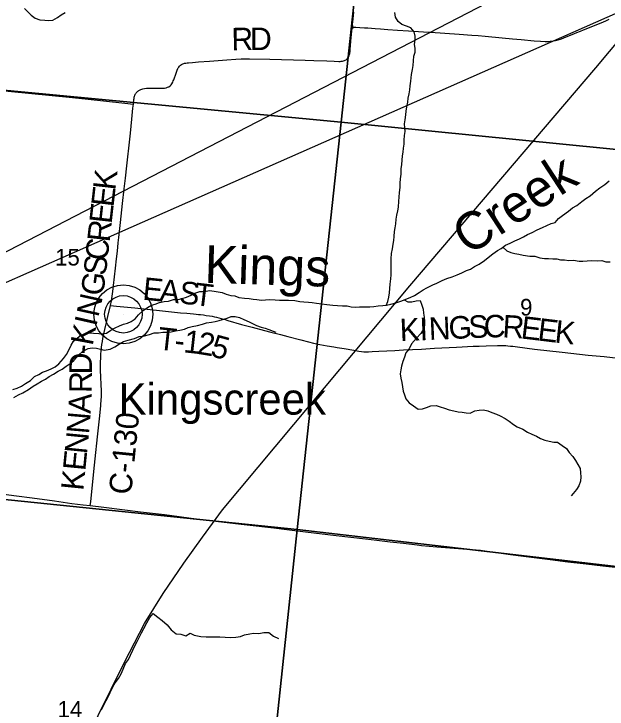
# Model space of a CAD drawing. Extents: x 831 to 1552, y 430 to 870.
# Drawn here: x 1016.19 to 1046.09, y 664.2 to 699.22 of the extents above; entities that cross this region are included whole.
import ezdxf

# ---------------------------------------------------------------- set-up
doc = ezdxf.new("R2010")
doc.units = 0
for name, color, linetype in [('GM_X_Corporation', 7, 'Continuous'), ('GM_X_County_Road', 7, 'Continuous'), ('GM_X_County_Road_Text', 7, 'Continuous'), ('GM_X_Minor_River', 7, 'Continuous'), ('GM_X_Minor_River_Text', 7, 'Continuous'), ('GM_X_Rail_Line', 7, 'Continuous'), ('GM_X_Section_Text', 7, 'Continuous'), ('GM_X_State_Route', 7, 'Continuous'), ('GM_X_Township_Road', 7, 'Continuous'), ('GM_X_Township_Road_Text', 7, 'Continuous'), ('GM_X_Unincorporated', 7, 'Continuous'), ('GM_X_Unincorporated_Location', 7, 'Continuous'), ('GM_X_Unincorporated_Text', 7, 'Continuous'), ('SH_Text', 7, 'Continuous')]:
    doc.layers.add(name, color=color, linetype=linetype)

msp = doc.modelspace()

# ---------------------------------------------------------------- linework, layer by layer
at = {"layer": 'GM_X_Corporation'}
for points in [[(1034.738, 712.834), (1032.694, 693.772), (1011.587, 695.769), (1013.944, 715)], [(1034.738, 712.834), (1054.834, 710.548), (1052.831, 691.774), (1032.694, 693.772)], [(1011.587, 695.769), (1032.694, 693.772), (1030.47, 673.244), (1009.676, 675.38)], [(1032.694, 693.772), (1052.831, 691.774), (1050.619, 670.912), (1030.47, 673.244)], [(1030.47, 673.244), (1028.346, 653.321), (1007.707, 655.818), (1009.676, 675.38)], [(1030.47, 673.244), (1050.619, 670.912), (1048.583, 651.419), (1028.346, 653.321)]]:
    msp.add_lwpolyline(points, close=True, dxfattribs=at)
at = {"layer": 'GM_X_County_Road'}
for points in [[(1033.297, 698.535), (1033.321, 698.543), (1033.344, 698.545), (1033.369, 698.547), (1033.392, 698.547), (1033.422, 698.546), (1033.632, 698.537), (1033.855, 698.527), (1034.028, 698.513), (1034.4, 698.484), (1034.673, 698.464), (1035.044, 698.439), (1035.527, 698.407), (1036.085, 698.37), (1036.841, 698.317), (1037.188, 698.293), (1038.639, 698.192), (1039.271, 698.148), (1039.593, 698.127), (1039.952, 698.099), (1040.794, 698.023), (1041.325, 697.971), (1041.759, 697.934), (1042.414, 697.872), (1042.737, 697.844), (1042.961, 697.833), (1043.136, 697.834), (1043.216, 697.84), (1043.311, 697.849), (1043.392, 697.863), (1043.484, 697.882), (1043.616, 697.918), (1043.783, 697.972), (1044.028, 698.064), (1044.41, 698.215), (1044.569, 698.282), (1044.754, 698.359), (1044.903, 698.42), (1045.791, 698.776), (1046.033, 698.877), (1046.19, 698.956)], [(1022.215, 694.682), (1022.223, 694.758), (1022.233, 694.837), (1022.243, 694.914), (1022.25, 694.966), (1022.26, 695.021), (1022.273, 695.071), (1022.286, 695.112), (1022.297, 695.14), (1022.311, 695.167), (1022.324, 695.191), (1022.34, 695.219), (1022.359, 695.244), (1022.377, 695.266), (1022.402, 695.291), (1022.419, 695.307), (1022.445, 695.328), (1022.467, 695.344), (1022.498, 695.364), (1022.53, 695.38), (1022.561, 695.395), (1022.595, 695.41), (1022.648, 695.428), (1022.688, 695.441), (1022.771, 695.46), (1022.881, 695.475), (1022.991, 695.481), (1023.189, 695.483), (1023.526, 695.48), (1023.641, 695.479), (1023.717, 695.479), (1023.787, 695.486), (1023.872, 695.504), (1023.943, 695.527), (1024.006, 695.554), (1024.063, 695.594), (1024.113, 695.642), (1024.159, 695.705), (1024.206, 695.788), (1024.229, 695.841), (1024.254, 695.903), (1024.365, 696.235), (1024.418, 696.386), (1024.454, 696.463), (1024.475, 696.509), (1024.5, 696.546), (1024.54, 696.594), (1024.588, 696.637), (1024.643, 696.674), (1024.706, 696.704), (1024.756, 696.722), (1024.794, 696.734), (1024.857, 696.747), (1024.92, 696.755), (1024.99, 696.76), (1025.203, 696.778), (1025.5, 696.799), (1026.046, 696.838), (1026.926, 696.904), (1027.384, 696.936), (1027.644, 696.95), (1027.793, 696.953), (1028.066, 696.953), (1029.097, 696.933), (1030.873, 696.892), (1031.307, 696.876), (1031.966, 696.854), (1032.34, 696.838), (1032.569, 696.828), (1032.64, 696.831), (1032.694, 696.836), (1032.755, 696.845), (1032.803, 696.854), (1032.85, 696.867), (1032.889, 696.885), (1032.932, 696.915), (1032.966, 696.94), (1032.999, 696.974), (1033.036, 697.019), (1033.067, 697.07), (1033.085, 697.109), (1033.104, 697.168), (1033.12, 697.231), (1033.127, 697.276), (1033.134, 697.318), (1033.139, 697.373), (1033.145, 697.431), (1033.176, 697.855), (1033.217, 698.356), (1033.222, 698.392), (1033.228, 698.429), (1033.235, 698.453), (1033.241, 698.473), (1033.247, 698.487), (1033.256, 698.502), (1033.266, 698.514), (1033.277, 698.523), (1033.297, 698.535)], [(1021.07, 684.536), (1021.112, 684.759), (1021.148, 684.997), (1021.182, 685.231), (1021.219, 685.538), (1021.268, 685.982), (1021.313, 686.409), (1021.368, 686.89), (1021.41, 687.274), (1021.455, 687.691), (1021.484, 687.965), (1021.563, 688.717), (1021.661, 689.663), (1021.749, 690.405), (1021.813, 690.943), (1021.889, 691.563), (1022.035, 692.915), (1022.065, 693.211), (1022.14, 693.923), (1022.19, 694.467), (1022.215, 694.682)], [(1020.043, 674.449), (1020.064, 674.638), (1020.23, 676.17), (1020.298, 676.813), (1020.411, 677.913), (1020.504, 678.828), (1020.571, 679.475), (1020.583, 679.612), (1020.588, 679.695), (1020.596, 679.795), (1020.602, 679.91), (1020.606, 680.006), (1020.606, 680.104), (1020.606, 680.222), (1020.602, 680.351), (1020.598, 680.441), (1020.594, 680.527), (1020.589, 680.653), (1020.583, 680.814), (1020.577, 680.979), (1020.567, 681.22), (1020.567, 681.47), (1020.564, 681.697), (1020.569, 681.87), (1020.578, 682.068), (1020.593, 682.265), (1020.611, 682.419), (1020.632, 682.572), (1020.653, 682.72), (1020.676, 682.862), (1020.713, 683.045), (1020.777, 683.32), (1020.863, 683.678), (1020.935, 683.974), (1021.07, 684.536)]]:
    msp.add_lwpolyline(points, dxfattribs=at)
at = {"layer": 'GM_X_Minor_River'}
for points in [[(1016.723, 699.494), (1017.07, 699.149), (1017.274, 699.01), (1017.51, 698.916), (1017.746, 698.906), (1017.951, 698.881), (1018.164, 698.91), (1018.386, 699.037), (1018.578, 699.179), (1018.785, 699.291)], [(1034.959, 684.539), (1035.04, 684.73), (1035.096, 684.943), (1035.121, 685.164), (1035.138, 685.392), (1035.163, 685.612), (1035.188, 685.871), (1035.205, 686.084), (1035.215, 686.366), (1035.21, 686.655), (1035.212, 686.876), (1035.23, 687.158), (1035.27, 687.378), (1035.302, 687.614), (1035.335, 687.812), (1035.352, 688.009), (1035.377, 688.253), (1035.409, 688.45), (1035.434, 688.648), (1035.466, 688.876), (1035.498, 689.089), (1035.546, 689.294), (1035.571, 689.492), (1035.596, 689.789), (1035.605, 689.986), (1035.63, 690.222), (1035.663, 690.473), (1035.665, 690.686), (1035.682, 690.907), (1035.707, 691.15), (1035.717, 691.424), (1035.742, 691.629), (1035.759, 691.85), (1035.784, 692.07), (1035.816, 692.26), (1035.833, 692.458), (1035.858, 692.663), (1035.867, 692.861), (1035.885, 693.089), (1035.909, 693.294), (1035.904, 693.484), (1035.882, 693.675), (1035.915, 693.888), (1035.948, 694.138), (1035.964, 694.328), (1035.997, 694.541), (1036.045, 694.776), (1036.069, 694.974), (1036.109, 695.187), (1036.142, 695.392), (1036.166, 695.597), (1036.199, 695.825), (1036.24, 696.174), (1036.28, 696.417), (1036.313, 696.622), (1036.33, 696.865), (1036.355, 697.086), (1036.418, 697.291), (1036.412, 697.488), (1036.391, 697.686), (1036.423, 697.914), (1036.41, 698.104), (1036.359, 698.325), (1036.193, 698.517), (1035.988, 698.61), (1035.753, 698.681), (1035.556, 698.843), (1035.429, 699.057), (1035.385, 699.286)], [(1036.82, 685.322), (1037.011, 685.419), (1037.302, 685.568), (1037.516, 685.658), (1037.776, 685.784), (1038.005, 685.889), (1038.28, 685.977), (1038.532, 686.074), (1038.762, 686.178), (1039.006, 686.29), (1039.205, 686.356), (1039.412, 686.491), (1039.634, 686.611), (1039.91, 686.799), (1040.101, 686.949), (1040.339, 687.137), (1040.561, 687.295), (1040.753, 687.407), (1040.975, 687.565), (1041.204, 687.676), (1041.441, 687.781), (1041.671, 687.885), (1041.87, 687.989), (1042.076, 688.109), (1042.313, 688.206), (1042.573, 688.34), (1042.826, 688.459), (1043.055, 688.556), (1043.277, 688.66), (1043.468, 688.719), (1043.645, 688.916), (1043.836, 689.058), (1044.15, 689.291), (1044.342, 689.457), (1044.557, 689.568), (1044.81, 689.764), (1045.017, 689.914), (1045.239, 690.064), (1045.5, 690.29), (1045.73, 690.462), (1045.975, 690.635), (1046.19, 690.808)], [(1040.838, 687.467), (1041.041, 687.29), (1041.231, 687.204), (1041.436, 687.149), (1041.641, 687.124), (1041.861, 687.068), (1042.196, 687.012), (1042.447, 687.009), (1042.698, 686.938), (1042.941, 686.897), (1043.139, 686.895), (1043.352, 686.878), (1043.55, 686.876), (1043.748, 686.836), (1043.938, 686.834), (1044.166, 686.801), (1044.395, 686.807), (1044.676, 686.766), (1044.874, 686.764), (1045.08, 686.777), (1045.323, 686.79), (1045.613, 686.779), (1045.826, 686.792), (1046.023, 686.729), (1046.237, 686.735)], [(1016.147, 680.296), (1016.353, 680.37), (1016.575, 680.467), (1016.782, 680.594), (1017.027, 680.76), (1017.234, 680.948), (1017.448, 681.053), (1017.639, 681.165), (1017.83, 681.232), (1018.075, 681.337), (1018.274, 681.434), (1018.466, 681.592), (1018.689, 681.857), (1018.851, 682.068), (1018.975, 682.319), (1019.083, 682.539), (1019.199, 682.736), (1019.391, 682.886), (1019.583, 683.052), (1019.781, 683.111), (1019.995, 683.147), (1020.2, 683.138), (1020.467, 683.127), (1020.665, 683.103), (1020.855, 683.139), (1021.085, 683.281), (1021.292, 683.409), (1021.521, 683.513), (1021.72, 683.588), (1021.918, 683.639), (1022.109, 683.721), (1022.309, 683.864), (1022.478, 684.068), (1022.716, 684.279), (1022.923, 684.43), (1023.129, 684.542), (1023.32, 684.593), (1023.527, 684.683), (1023.763, 684.726), (1023.984, 684.755), (1024.236, 684.828), (1024.465, 684.826), (1024.678, 684.885), (1024.892, 684.959), (1025.129, 685.056), (1025.32, 685.153), (1025.565, 685.242), (1025.793, 685.24), (1026.045, 685.283), (1026.288, 685.258), (1026.494, 685.218), (1026.684, 685.178), (1026.888, 685.107), (1027.131, 685.029), (1027.329, 685.012), (1027.527, 684.941), (1027.808, 684.893), (1028.059, 684.883), (1028.249, 684.858), (1028.439, 684.826), (1028.675, 684.808), (1029.071, 684.835), (1029.353, 684.824), (1029.574, 684.799), (1029.84, 684.804), (1030.038, 684.795), (1030.35, 684.784), (1030.609, 684.736), (1030.807, 684.719), (1031.035, 684.694), (1031.225, 684.676), (1031.438, 684.651), (1031.719, 684.611), (1031.963, 684.578), (1032.275, 684.552), (1032.511, 684.527), (1032.754, 684.509), (1032.983, 684.507), (1033.188, 684.467), (1033.401, 684.449), (1033.614, 684.47), (1033.888, 684.46), (1034.132, 684.457), (1034.33, 684.478), (1034.559, 684.514), (1034.78, 684.527), (1034.978, 684.54), (1035.192, 684.592), (1035.444, 684.673), (1035.741, 684.769), (1035.948, 684.843), (1036.162, 684.932), (1036.376, 685.037), (1036.613, 685.194), (1036.82, 685.322)], [(1035.86, 684.811), (1036.053, 684.713), (1036.251, 684.718), (1036.465, 684.769), (1036.67, 684.775), (1036.76, 684.546), (1036.819, 684.347), (1036.84, 684.149), (1036.869, 683.95), (1036.89, 683.744), (1036.88, 683.531), (1036.84, 683.341), (1036.709, 683.114), (1036.486, 682.88), (1036.24, 682.593), (1036.108, 682.343), (1035.954, 682.139), (1035.883, 681.926), (1035.798, 681.714), (1035.72, 681.478), (1035.687, 681.288), (1035.655, 681.091), (1035.691, 680.877), (1035.75, 680.655), (1035.779, 680.426), (1035.815, 680.22), (1035.874, 680.029), (1035.948, 679.823), (1036.122, 679.631), (1036.341, 679.476), (1036.561, 679.314), (1036.782, 679.319), (1036.988, 679.386), (1037.209, 679.475), (1037.468, 679.488), (1037.681, 679.432), (1037.901, 679.362), (1038.129, 679.283), (1038.357, 679.228), (1038.577, 679.18), (1038.783, 679.155), (1038.98, 679.13), (1039.186, 679.113), (1039.43, 679.217), (1039.636, 679.261), (1039.865, 679.274), (1040.085, 679.226), (1040.283, 679.148), (1040.51, 679.062), (1040.7, 678.968), (1040.95, 678.836), (1041.147, 678.697), (1041.366, 678.535), (1041.563, 678.411), (1041.836, 678.294), (1042.071, 678.147), (1042.298, 678.046), (1042.533, 677.944), (1042.738, 677.828), (1042.943, 677.75), (1043.163, 677.694), (1043.399, 677.654), (1043.597, 677.652), (1043.831, 677.474), (1044.036, 677.327), (1044.178, 677.12), (1044.359, 676.92), (1044.495, 676.728), (1044.615, 676.521), (1044.727, 676.315), (1044.756, 676.101), (1044.769, 675.895), (1044.752, 675.674), (1044.666, 675.454), (1044.543, 675.257), (1044.373, 675.053), (1044.273, 674.948)], [(1016.189, 679.891), (1016.426, 680.034), (1016.648, 680.138), (1016.931, 680.303), (1017.169, 680.469), (1017.368, 680.581), (1017.582, 680.724), (1017.781, 680.821), (1017.98, 680.949), (1018.194, 681.069), (1018.424, 681.227), (1018.631, 681.331), (1018.83, 681.467), (1019.022, 681.61), (1019.221, 681.76), (1019.467, 682.047), (1019.659, 682.221), (1019.935, 682.371), (1020.133, 682.391), (1020.354, 682.389), (1020.559, 682.326), (1020.749, 682.287), (1021.038, 682.337), (1021.276, 682.457), (1021.513, 682.599), (1021.72, 682.719), (1021.956, 682.778), (1022.269, 682.874), (1022.514, 682.963), (1022.712, 682.992), (1023.033, 683.072), (1023.269, 683.154), (1023.482, 683.152), (1023.704, 683.18), (1023.917, 683.193), (1024.123, 683.199), (1024.336, 683.25), (1024.565, 683.286), (1024.786, 683.337), (1024.985, 683.419), (1025.176, 683.478), (1025.45, 683.529), (1025.695, 683.595), (1025.908, 683.654), (1026.152, 683.69), (1026.343, 683.726), (1026.542, 683.77), (1026.946, 683.888), (1027.137, 683.977), (1027.351, 683.983), (1027.571, 683.928), (1027.783, 683.826), (1028.049, 683.71), (1028.428, 683.531), (1028.648, 683.445), (1028.86, 683.382), (1029.05, 683.319), (1029.255, 683.241), (1029.392, 683.194)], [(1020.611, 664.159), (1020.752, 664.43), (1020.845, 664.626), (1020.939, 664.823), (1021.041, 665.042), (1021.182, 665.313), (1021.306, 665.516), (1021.461, 665.742), (1021.594, 665.984), (1021.703, 666.218), (1021.821, 666.497), (1021.968, 666.692), (1022.07, 666.919), (1022.188, 667.168), (1022.282, 667.387), (1022.406, 667.598), (1022.516, 667.809), (1022.625, 668.043), (1022.742, 668.262), (1022.891, 668.541), (1023.039, 668.812), (1023.216, 669.015), (1023.442, 668.837), (1023.667, 668.667), (1023.922, 668.451), (1024.116, 668.197), (1024.379, 667.989), (1024.614, 667.97), (1024.856, 667.891), (1025.078, 668.025), (1025.281, 667.931), (1025.607, 667.85), (1025.88, 667.839), (1026.1, 667.844), (1026.351, 667.833), (1026.571, 667.837), (1026.837, 667.826), (1027.132, 667.799), (1027.383, 667.818), (1027.619, 667.853), (1027.81, 667.934), (1028.077, 667.999), (1028.267, 668.026), (1028.533, 668.015), (1028.784, 668.05), (1029.042, 668.054), (1029.282, 667.876), (1029.524, 667.758)]]:
    msp.add_lwpolyline(points, dxfattribs=at)
at = {"layer": 'GM_X_Rail_Line'}
msp.add_lwpolyline([(1019.767, 662.513), (1021.761, 666.57), (1022.769, 668.517), (1023.711, 670.015), (1024.761, 671.556), (1025.705, 672.853), (1026.7, 674.233), (1031.154, 679.565), (1036.15, 685.527), (1045.521, 696.507), (1057.393, 710.715), (1059.26, 712.976), (1060.098, 713.979), (1060.856, 715.052), (1068.102, 725.035), (1069.841, 727.406), (1071.639, 730.006), (1075.116, 734.935), (1078.227, 739.322), (1079.494, 741.028), (1080.443, 742.199), (1081.307, 743.182), (1081.766, 743.624)], dxfattribs=at)
at = {"layer": 'GM_X_State_Route'}
for points in [[(1009.732, 675.531), (1009.812, 675.534), (1010.358, 675.557), (1010.643, 675.561), (1010.904, 675.557), (1011.201, 675.545), (1011.573, 675.52), (1012.005, 675.481), (1012.524, 675.423), (1013.67, 675.279), (1015.026, 675.106), (1016.32, 674.944), (1017.108, 674.837), (1018.241, 674.683), (1019.115, 674.564), (1019.682, 674.492), (1020.043, 674.449)], [(1020.043, 674.449), (1020.731, 674.365), (1022.582, 674.143), (1023.778, 674.001), (1025.379, 673.791), (1026.785, 673.614), (1027.797, 673.503), (1029.302, 673.324), (1029.808, 673.262), (1030.891, 673.134), (1032.431, 672.951), (1033.911, 672.779), (1034.491, 672.711), (1035.157, 672.633), (1035.823, 672.553), (1036.514, 672.471), (1036.737, 672.448), (1037.505, 672.381), (1038.603, 672.296), (1039.499, 672.224), (1039.701, 672.204), (1039.93, 672.177), (1040.41, 672.111), (1041.221, 671.995), (1041.872, 671.902), (1043.214, 671.734), (1044.115, 671.623), (1045.041, 671.522), (1045.88, 671.423), (1046.793, 671.312)]]:
    msp.add_lwpolyline(points, dxfattribs=at)
at = {"layer": 'GM_X_Township_Road'}
for points in [[(1033.297, 698.535), (1033.287, 698.553), (1033.278, 698.578), (1033.269, 698.606), (1033.267, 698.626), (1033.264, 698.649), (1033.265, 698.718), (1033.273, 698.804), (1033.328, 699.306)], [(1011.631, 695.744), (1012.666, 695.647), (1013.928, 695.524), (1014.856, 695.437), (1016.081, 695.319), (1018.979, 695.024), (1019.783, 694.941), (1021.79, 694.728), (1022.215, 694.682)], [(1021.07, 684.536), (1021.366, 684.504), (1021.915, 684.446), (1022.292, 684.406), (1023.529, 684.273), (1023.99, 684.229), (1024.595, 684.167), (1024.904, 684.137), (1025.086, 684.121), (1025.253, 684.107), (1025.385, 684.095), (1025.499, 684.085), (1025.595, 684.074), (1025.748, 684.055), (1025.877, 684.036), (1026.059, 684.01), (1026.184, 683.988), (1026.306, 683.965), (1026.405, 683.945), (1026.523, 683.917), (1026.647, 683.883), (1026.784, 683.841), (1026.974, 683.782), (1027.666, 683.578), (1028.194, 683.434), (1028.819, 683.27), (1029.144, 683.187), (1029.626, 683.065), (1030, 682.974), (1030.662, 682.806), (1031.046, 682.701), (1031.298, 682.633), (1031.614, 682.564), (1031.981, 682.497), (1032.324, 682.442), (1032.483, 682.417), (1032.838, 682.361), (1033.327, 682.274), (1033.584, 682.227), (1033.708, 682.211), (1033.833, 682.202), (1034.058, 682.201), (1034.257, 682.208), (1034.58, 682.227), (1035.399, 682.272), (1035.821, 682.294), (1036.74, 682.339), (1037.384, 682.377), (1038.501, 682.438), (1039.333, 682.478), (1039.649, 682.489), (1040.003, 682.501), (1040.573, 682.519), (1040.74, 682.516), (1040.872, 682.516), (1040.984, 682.511), (1041.086, 682.504), (1041.22, 682.491), (1041.34, 682.476), (1041.579, 682.444), (1042.437, 682.329), (1043.833, 682.174), (1045.13, 682.036), (1045.934, 681.954), (1047.071, 681.833)]]:
    msp.add_lwpolyline(points, dxfattribs=at)
at = {"layer": 'GM_X_Unincorporated'}
for radius in [1.488, 0.943]:
    msp.add_circle((1021.71, 684.088), radius, dxfattribs=at)
at = {"layer": 'GM_X_Unincorporated_Location'}
msp.add_line((1021.71, 684.088), (1021.71, 684.088), dxfattribs=at)
at = {"layer": 'SH_Text'}
msp.add_lwpolyline([(995.67, 676.817), (1119.5, 731.442), (1119.5, 740.878)], close=True, dxfattribs=at)

# ---------------------------------------------------------------- texts
at = {"layer": 'GM_X_County_Road_Text'}
for s, height, rotation, p in [('R', 1.136, 1.0031, (1027.165, 697.38)), ('D', 1.136, 0.0474, (1028.093, 697.397)), ('K', 1.136, 83.5974, (1021.307, 690.308)), ('E', 1.136, 83.5969, (1021.212, 689.464)), ('E', 1.136, 83.5969, (1021.117, 688.619)), ('R', 1.136, 83.5987, (1021.013, 687.692)), ('C', 1.136, 83.5987, (1020.909, 686.764)), ('S', 1.136, 83.5377, (1020.823, 686.001)), ('G', 1.136, 82.1002, (1020.681, 684.98)), ('N', 1.136, 77.6063, (1020.45, 683.907)), ('I', 1.136, 77.185, (1020.344, 683.443)), ('K', 1.136, 79.3638, (1020.162, 682.472)), ('-', 1.136, 85.2091, (1020.127, 682.037)), ('D', 1.136, 89.831, (1020.125, 681.061)), ('R', 1.136, 89.6123, (1020.119, 680.123)), ('A', 1.136, 86.9826, (1020.064, 679.068)), ('N', 1.136, 85.0315, (1019.975, 678.029)), ('C-130', 1.1364, 84.2353, (1022.102, 674.969)), ('N', 1.136, 84.3605, (1019.875, 677.02)), ('E', 1.136, 84.338, (1019.791, 676.173)), ('K', 1.136, 84.3409, (1019.693, 675.178))]:
    msp.add_text(s, height=height, rotation=rotation, dxfattribs=at).set_placement(p)
at = {"layer": 'GM_X_Minor_River_Text'}
for s, height, rotation, p in [('Creek', 1.8923, 33.1206, (1039.108, 687.016)), ('Kings', 1.894, 358.1764, (1025.78, 685.679))]:
    msp.add_text(s, height=height, rotation=rotation, dxfattribs=at).set_placement(p)
at = {"layer": 'GM_X_Section_Text'}
for s, height, p in [('15', 0.8371, (1018.271, 686.546)), ('9', 0.837, (1041.704, 684.027)), ('14', 0.8371, (1018.396, 663.775))]:
    msp.add_text(s, height=height, rotation=0, dxfattribs=at).set_placement(p)
at = {"layer": 'GM_X_Township_Road_Text'}
for s, rotation, p in [('E', 354.1875, (1022.65, 684.829)), ('A', 354.1836, (1023.495, 684.743)), ('S', 353.9547, (1024.489, 684.642)), ('T', 353.027, (1025.246, 684.561)), ('N', 2.4952, (1037.126, 682.794)), ('G', 2.496, (1038.125, 682.838)), ('S', 2.4858, (1039.124, 682.881)), ('C', 1.0499, (1039.883, 682.914)), ('R', 356.4383, (1040.792, 682.932)), ('E', 353.2216, (1041.706, 682.876)), ('K', 2.496, (1035.661, 682.73)), ('I', 2.4947, (1036.66, 682.774)), ('E', 353.1137, (1042.55, 682.775)), ('K', 353.9936, (1043.413, 682.671)), ('T', 353.666, (1023.405, 682.324)), ('1', 353.565, (1024.713, 682.178)), ('2', 350.7225, (1025.394, 682.102)), ('5', 344.6687, (1026.053, 681.996)), ('-', 353.6408, (1024.249, 682.23))]:
    msp.add_text(s, height=1.136, rotation=rotation, dxfattribs=at).set_placement(p)
at = {"layer": 'GM_X_Unincorporated_Text'}
msp.add_text('Kingscreek', height=1.5795, rotation=0, dxfattribs=at).set_placement((1021.471, 679.033))

doc.saveas('drawing.dxf')
